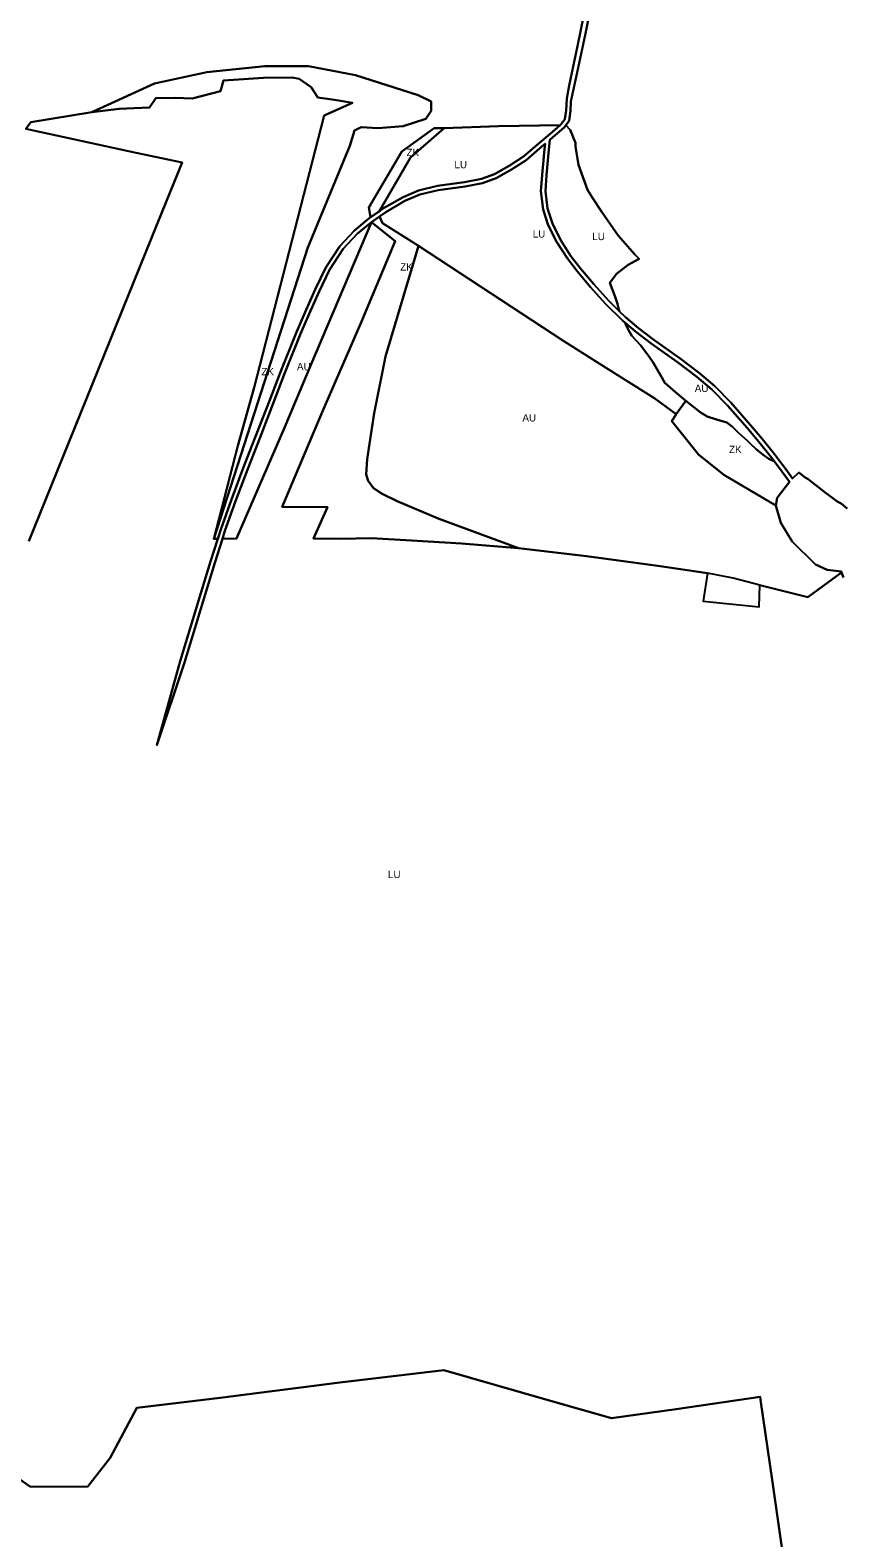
# Model space of a CAD drawing. Extents: x -532067 to -529270, y -1180561 to -1176456.
# Drawn here: x -530711 to -530157, y -1180006 to -1178979 of the extents above; entities that cross this region are included whole.
import ezdxf

# ---------------------------------------------------------------- set-up
doc = ezdxf.new("R2010")
doc.units = 0
for name, color, linetype in [('90630013', 7, 'Continuous'), ('90710013', 7, 'Continuous'), ('90750013', 7, 'Continuous'), ('90770013', 7, 'Continuous')]:
    doc.layers.add(name, color=color, linetype=linetype)

msp = doc.modelspace()

# ---------------------------------------------------------------- linework, layer by layer
at = {"layer": '90630013'}
for points in [[(-530156.3793, -1179351.78245), (-530157.6823, -1179348.30645), (-530157.8833, -1179347.77045), (-530167.3973, -1179346.65945), (-530175.3513, -1179342.90645), (-530191.2603, -1179327.14345), (-530199.0643, -1179314.53245), (-530202.3663, -1179302.67245), (-530201.4653, -1179297.56845), (-530193.1353, -1179286.54745), (-530198.0423, -1179279.73345), (-530203.3883, -1179272.71645), (-530205.7263, -1179269.64745), (-530214.0793, -1179259.22445), (-530221.9563, -1179249.81545), (-530235.4133, -1179234.46045), (-530245.9893, -1179223.61445), (-530256.2593, -1179214.87745), (-530269.4723, -1179204.98045), (-530287.4103, -1179192.17245), (-530298.0283, -1179184.12045), (-530305.4793, -1179177.85945), (-530306.9943, -1179176.58645), (-530318.5383, -1179165.17045), (-530328.8303, -1179153.81345), (-530337.9493, -1179143.05445), (-530344.5543, -1179134.39445), (-530351.8613, -1179123.13645), (-530357.5563, -1179111.59845), (-530361.0233, -1179100.80945), (-530362.5733, -1179088.50745), (-530361.8273, -1179077.33345), (-530360.0803, -1179059.81445), (-530359.7163, -1179056.17045), (-530361.6403, -1179057.82245), (-530372.6973, -1179067.31245), (-530382.6153, -1179073.61245), (-530393.0673, -1179079.63545), (-530402.3983, -1179082.92445), (-530414.2783, -1179085.26545), (-530432.6523, -1179087.80845), (-530445.1503, -1179090.72345), (-530455.2663, -1179095.12045), (-530468.2793, -1179102.64945), (-530472.5783, -1179105.64845), (-530478.1133, -1179109.50945), (-530479.3253, -1179110.35545), (-530487.8303, -1179117.53845), (-530497.4083, -1179127.77145), (-530506.6493, -1179141.98545), (-530513.7343, -1179156.76845), (-530520.6283, -1179172.07145), (-530526.4113, -1179185.60445), (-530537.5443, -1179213.39145), (-530544.8173, -1179232.46145), (-530554.3253, -1179256.83045), (-530562.4973, -1179277.70845), (-530570.8283, -1179299.72045), (-530578.0133, -1179320.06145), (-530579.6963, -1179325.36045), (-530584.9193, -1179341.80645), (-530593.0713, -1179368.59045), (-530605.5913, -1179409.72645), (-530624.4063, -1179466.13845), (-530608.4613, -1179408.85245), (-530595.9413, -1179367.71645), (-530587.7833, -1179340.91645), (-530582.8543, -1179325.39445), (-530580.8573, -1179319.10745), (-530573.6463, -1179298.69045), (-530565.2973, -1179276.63045), (-530557.1193, -1179255.73845), (-530547.6153, -1179231.38145), (-530540.3383, -1179212.29945), (-530529.1833, -1179184.45645), (-530523.3763, -1179170.86545), (-530516.4543, -1179155.50445), (-530509.2713, -1179140.51345), (-530499.7783, -1179125.91545), (-530489.9003, -1179115.36045), (-530481.1553, -1179107.97345), (-530478.6963, -1179106.25745), (-530472.8493, -1179102.17845), (-530469.8913, -1179100.11545), (-530456.6203, -1179092.43845), (-530446.0963, -1179087.86345), (-530433.2003, -1179084.85645), (-530414.7743, -1179082.30545), (-530403.1903, -1179080.02245), (-530394.3253, -1179076.89745), (-530384.1693, -1179071.04445), (-530374.4873, -1179064.89645), (-530363.5943, -1179055.54645), (-530356.6093, -1179049.55045), (-530349.5233, -1179043.46745), (-530348.7823, -1179042.83145), (-530346.1903, -1179039.23445), (-530345.3193, -1179033.50145), (-530345.0483, -1179025.15345), (-530343.2833, -1179016.29745), (-530337.4573, -1178988.49945), (-530327.5643, -1178940.45745)], [(-530326.8543, -1178953.76245), (-530332.4003, -1178981.99545), (-530338.9743, -1179012.70045), (-530342.1203, -1179027.39345), (-530342.3273, -1179033.77545), (-530343.3323, -1179040.40045), (-530345.5203, -1179043.43745), (-530346.5563, -1179044.87545), (-530354.6553, -1179051.82645), (-530356.4183, -1179053.34045), (-530357.0943, -1179060.11245), (-530358.8373, -1179077.58145), (-530359.5613, -1179088.41945), (-530358.0813, -1179100.15745), (-530354.7683, -1179110.47045), (-530349.2493, -1179121.65045), (-530342.1003, -1179132.66645), (-530335.6113, -1179141.17445), (-530326.5743, -1179151.83545), (-530316.3703, -1179163.09445), (-530308.9903, -1179170.39245), (-530304.9703, -1179174.36845), (-530296.1563, -1179181.77445), (-530285.6323, -1179189.75645), (-530267.7003, -1179202.55845), (-530254.3853, -1179212.53145), (-530243.9393, -1179221.42045), (-530233.2093, -1179232.42245), (-530219.6783, -1179247.86345), (-530211.7593, -1179257.32245), (-530203.3623, -1179267.79945), (-530197.8743, -1179275.00445), (-530195.6323, -1179277.94745), (-530191.1033, -1179284.23645), (-530186.8593, -1179280.13745), (-530182.5293, -1179283.55045), (-530180.5183, -1179284.79145), (-530178.1983, -1179286.65345), (-530175.2603, -1179288.82545), (-530173.0953, -1179290.53145), (-530168.7653, -1179293.78945), (-530164.5893, -1179297.04745), (-530161.6513, -1179299.21945), (-530159.6413, -1179300.46045), (-530157.9403, -1179301.39145), (-530153.9193, -1179304.64945)]]:
    msp.add_lwpolyline(points, dxfattribs=at)
at = {"layer": '90710013'}
for points in [[(-530489.0883, -1179009.38045), (-530446.2343, -1179022.97245), (-530437.5243, -1179027.32045), (-530437.5243, -1179033.65945), (-530441.0093, -1179039.04745), (-530449.4023, -1179041.78845), (-530456.5343, -1179044.11745), (-530473.6433, -1179045.38545), (-530485.0493, -1179044.75145), (-530489.8013, -1179046.97045), (-530492.9703, -1179057.42845), (-530521.4843, -1179126.83545), (-530585.6813, -1179325.42545), (-530569.3263, -1179262.08445), (-530558.1493, -1179222.29945), (-530520.3563, -1179075.69445), (-530510.4263, -1179036.80445), (-530491.0873, -1179028.23845), (-530503.3233, -1179026.20245), (-530514.7293, -1179024.56745), (-530519.2893, -1179017.55745), (-530527.3723, -1179011.89745), (-530532.2523, -1179010.97945), (-530551.6213, -1179011.13245), (-530578.9203, -1179012.96845), (-530581.0553, -1179020.31145), (-530600.2723, -1179025.36045), (-530611.8623, -1179024.74845), (-530625.1313, -1179025.05445), (-530629.4813, -1179031.33945), (-530650.1973, -1179032.27345), (-530668.8183, -1179034.60845), (-530626.0133, -1179015.13045), (-530590.4763, -1179007.28945), (-530550.7573, -1179003.10645), (-530520.9683, -1179003.10645)], [(-530472.8493, -1179102.17845), (-530478.6963, -1179106.25745), (-530479.8873, -1179099.61445), (-530457.3843, -1179061.31545), (-530435.3293, -1179045.37145), (-530428.5473, -1179045.37145), (-530451.5693, -1179065.37345)], [(-530432.7003, -1179311.59845), (-530377.9583, -1179331.84545), (-530416.6893, -1179328.60745), (-530450.7263, -1179326.54745), (-530478.0133, -1179325.07545), (-530499.7263, -1179325.37045), (-530517.5983, -1179325.25645), (-530508.0163, -1179303.83945), (-530539.1163, -1179303.50245), (-530511.7153, -1179239.08245), (-530485.3013, -1179178.41445), (-530461.9923, -1179122.46445), (-530478.0863, -1179109.65945), (-530478.1133, -1179109.50945), (-530472.5783, -1179105.64845), (-530470.5323, -1179110.26745), (-530454.6033, -1179120.15945), (-530446.0883, -1179125.73245), (-530447.9173, -1179131.84645), (-530468.6513, -1179201.15145), (-530476.2613, -1179239.73845), (-530480.9853, -1179271.17345), (-530481.7723, -1179281.67345), (-530480.4603, -1179285.87345), (-530476.7863, -1179290.86145), (-530470.7503, -1179294.79845), (-530460.5163, -1179299.78545)], [(-530201.4653, -1179297.56845), (-530202.3663, -1179302.67245), (-530237.8683, -1179281.80345), (-530255.2043, -1179267.98945), (-530273.4423, -1179245.27145), (-530270.3163, -1179240.44645), (-530263.8223, -1179231.27845), (-530253.9763, -1179239.02645), (-530249.3363, -1179241.97445), (-530242.8413, -1179244.14645), (-530235.8823, -1179246.16245), (-530232.0163, -1179249.11045), (-530227.8403, -1179253.14345), (-530221.8093, -1179258.72845), (-530219.6443, -1179260.74545), (-530215.9323, -1179264.31345), (-530211.1383, -1179268.19245), (-530207.2723, -1179270.98445), (-530203.3883, -1179272.71645), (-530198.0423, -1179279.73345), (-530193.1353, -1179286.54745)]]:
    msp.add_lwpolyline(points, close=True, dxfattribs=at)
at = {"layer": '90750013'}
for points in [[(-530327.5643, -1178940.45745), (-530337.4573, -1178988.49945), (-530343.2833, -1179016.29745), (-530345.0483, -1179025.15345), (-530345.3193, -1179033.50145), (-530346.1903, -1179039.23445), (-530348.7823, -1179042.83145), (-530349.5233, -1179043.46745), (-530391.6263, -1179044.11145), (-530428.5473, -1179045.37145), (-530435.3293, -1179045.37145), (-530457.3843, -1179061.31545), (-530479.8873, -1179099.61445), (-530478.6963, -1179106.25745), (-530481.1553, -1179107.97345), (-530489.9003, -1179115.36045), (-530499.7783, -1179125.91545), (-530509.2713, -1179140.51345), (-530516.4543, -1179155.50445), (-530523.3763, -1179170.86545), (-530529.1833, -1179184.45645), (-530540.3383, -1179212.29945), (-530547.6153, -1179231.38145), (-530557.1193, -1179255.73845), (-530565.2973, -1179276.63045), (-530573.6463, -1179298.69045), (-530580.8573, -1179319.10745), (-530582.8543, -1179325.39445), (-530585.6813, -1179325.42545), (-530521.4843, -1179126.83545), (-530492.9703, -1179057.42845), (-530489.8013, -1179046.97045), (-530485.0493, -1179044.75145), (-530473.6433, -1179045.38545), (-530456.5343, -1179044.11745), (-530449.4023, -1179041.78845), (-530441.0093, -1179039.04745), (-530437.5243, -1179033.65945), (-530437.5243, -1179027.32045), (-530446.2343, -1179022.97245), (-530489.0883, -1179009.38045), (-530520.9683, -1179003.10645), (-530550.7573, -1179003.10645), (-530590.4763, -1179007.28945), (-530626.0133, -1179015.13045), (-530668.8183, -1179034.60845), (-530710.4553, -1179041.28045), (-530713.8673, -1179045.84445), (-530638.6183, -1179062.40745), (-530607.2773, -1179068.78745), (-530624.0833, -1179110.25145), (-530692.4043, -1179279.29745), (-530711.6183, -1179327.08245)], [(-530153.9193, -1179304.64945), (-530157.9403, -1179301.39145), (-530159.6413, -1179300.46045), (-530161.6513, -1179299.21945), (-530164.5893, -1179297.04745), (-530168.7653, -1179293.78945), (-530173.0953, -1179290.53145), (-530175.2603, -1179288.82545), (-530178.1983, -1179286.65345), (-530180.5183, -1179284.79145), (-530182.5293, -1179283.55045), (-530186.8593, -1179280.13745), (-530191.1033, -1179284.23645), (-530195.6323, -1179277.94745), (-530197.8743, -1179275.00445), (-530203.3623, -1179267.79945), (-530211.7593, -1179257.32245), (-530219.6783, -1179247.86345), (-530233.2093, -1179232.42245), (-530243.9393, -1179221.42045), (-530254.3853, -1179212.53145), (-530267.7003, -1179202.55845), (-530285.6323, -1179189.75645), (-530296.1563, -1179181.77445), (-530304.9703, -1179174.36845), (-530308.9903, -1179170.39245), (-530309.5303, -1179169.18845), (-530310.4393, -1179165.17445), (-530311.8943, -1179160.43045), (-530315.7133, -1179150.94345), (-530310.9853, -1179144.74045), (-530303.1643, -1179138.72045), (-530295.5263, -1179134.52345), (-530298.5173, -1179131.66645), (-530309.8693, -1179118.71545), (-530320.7763, -1179102.86145), (-530327.8993, -1179092.36745), (-530330.7923, -1179087.45445), (-530337.0253, -1179070.48445), (-530339.0283, -1179057.97945), (-530339.0283, -1179055.52345), (-530342.5903, -1179046.59145), (-530345.5203, -1179043.43745), (-530343.3323, -1179040.40045), (-530342.3273, -1179033.77545), (-530342.1203, -1179027.39345), (-530338.9743, -1179012.70045), (-530332.4003, -1178981.99545), (-530326.8543, -1178953.76245)], [(-530738.3333, -1179952.54645), (-530710.5303, -1179971.53645), (-530671.4873, -1179971.33845), (-530656.2083, -1179951.88945), (-530638.1853, -1179917.86845), (-530581.2093, -1179911.06445), (-530499.6223, -1179900.56645), (-530428.7603, -1179892.11645), (-530357.5583, -1179912.56445), (-530314.3973, -1179924.94345), (-530270.4793, -1179918.60045), (-530213.0623, -1179910.37245), (-530212.6033, -1179914.01045), (-530205.0143, -1179966.75845), (-530192.0373, -1180057.25345)]]:
    msp.add_lwpolyline(points, dxfattribs=at)
for points in [[(-530570.0483, -1179325.25645), (-530579.6963, -1179325.36045), (-530578.0133, -1179320.06145), (-530570.8283, -1179299.72045), (-530562.4973, -1179277.70845), (-530554.3253, -1179256.83045), (-530544.8173, -1179232.46145), (-530537.5443, -1179213.39145), (-530526.4113, -1179185.60445), (-530520.6283, -1179172.07145), (-530513.7343, -1179156.76845), (-530506.6493, -1179141.98545), (-530497.4083, -1179127.77145), (-530487.8303, -1179117.53845), (-530479.3253, -1179110.35545), (-530478.1133, -1179109.50945), (-530478.0863, -1179109.65945), (-530519.1543, -1179206.25045), (-530537.7453, -1179250.23245), (-530560.6433, -1179303.16745)], [(-530157.6823, -1179348.30645), (-530180.6043, -1179365.16645), (-530213.2693, -1179356.91845), (-530231.5543, -1179352.19945), (-530248.9843, -1179348.76645), (-530282.9893, -1179343.83245), (-530331.5983, -1179337.14345), (-530377.9583, -1179331.84545), (-530432.7003, -1179311.59845), (-530460.5163, -1179299.78545), (-530470.7503, -1179294.79845), (-530476.7863, -1179290.86145), (-530480.4603, -1179285.87345), (-530481.7723, -1179281.67345), (-530480.9853, -1179271.17345), (-530476.2613, -1179239.73845), (-530468.6513, -1179201.15145), (-530447.9173, -1179131.84645), (-530446.0883, -1179125.73245), (-530347.6493, -1179190.15545), (-530322.8373, -1179205.97545), (-530284.9993, -1179229.75745), (-530270.3163, -1179240.44645), (-530273.4423, -1179245.27145), (-530255.2043, -1179267.98945), (-530237.8683, -1179281.80345), (-530202.3663, -1179302.67245), (-530199.0643, -1179314.53245), (-530191.2603, -1179327.14345), (-530175.3513, -1179342.90645), (-530167.3973, -1179346.65945), (-530157.8833, -1179347.77045)], [(-530205.7263, -1179269.64745), (-530203.3883, -1179272.71645), (-530207.2723, -1179270.98445), (-530211.1383, -1179268.19245), (-530215.9323, -1179264.31345), (-530219.6443, -1179260.74545), (-530221.8093, -1179258.72845), (-530227.8403, -1179253.14345), (-530232.0163, -1179249.11045), (-530235.8823, -1179246.16245), (-530242.8413, -1179244.14645), (-530249.3363, -1179241.97445), (-530253.9763, -1179239.02645), (-530263.8223, -1179231.27845), (-530270.7973, -1179225.48845), (-530278.0123, -1179218.97445), (-530281.1383, -1179213.90745), (-530283.5433, -1179209.56445), (-530286.1893, -1179205.22245), (-530289.0753, -1179200.87945), (-530294.6073, -1179193.40045), (-530297.4933, -1179190.50445), (-530300.6193, -1179187.12745), (-530303.0243, -1179182.78445), (-530304.7083, -1179179.40645), (-530305.4793, -1179177.85945), (-530298.0283, -1179184.12045), (-530287.4103, -1179192.17245), (-530269.4723, -1179204.98045), (-530256.2593, -1179214.87745), (-530245.9893, -1179223.61445), (-530235.4133, -1179234.46045), (-530221.9563, -1179249.81545), (-530214.0793, -1179259.22445)]]:
    msp.add_lwpolyline(points, close=True, dxfattribs=at)
at = {"layer": '90770013'}
for points in [[(-530711.6183, -1179327.08245), (-530692.4043, -1179279.29745), (-530624.0833, -1179110.25145), (-530607.2773, -1179068.78745), (-530638.6183, -1179062.40745), (-530713.8673, -1179045.84445), (-530710.4553, -1179041.28045), (-530668.8183, -1179034.60845), (-530650.1973, -1179032.27345), (-530629.4813, -1179031.33945), (-530625.1313, -1179025.05445), (-530611.8623, -1179024.74845), (-530600.2723, -1179025.36045), (-530581.0553, -1179020.31145), (-530578.9203, -1179012.96845), (-530551.6213, -1179011.13245), (-530532.2523, -1179010.97945), (-530527.3723, -1179011.89745), (-530519.2893, -1179017.55745), (-530514.7293, -1179024.56745), (-530503.3233, -1179026.20245), (-530491.0873, -1179028.23845), (-530510.4263, -1179036.80445), (-530520.3563, -1179075.69445), (-530558.1493, -1179222.29945), (-530569.3263, -1179262.08445), (-530585.6813, -1179325.42545), (-530582.8543, -1179325.39445), (-530587.7833, -1179340.91645), (-530595.9413, -1179367.71645), (-530608.4613, -1179408.85245), (-530624.4063, -1179466.13845), (-530605.5913, -1179409.72645), (-530593.0713, -1179368.59045), (-530584.9193, -1179341.80645), (-530579.6963, -1179325.36045), (-530570.0483, -1179325.25645), (-530560.6433, -1179303.16745), (-530537.7453, -1179250.23245), (-530519.1543, -1179206.25045), (-530478.0863, -1179109.65945), (-530461.9923, -1179122.46445), (-530485.3013, -1179178.41445), (-530511.7153, -1179239.08245), (-530539.1163, -1179303.50245), (-530508.0163, -1179303.83945), (-530517.5983, -1179325.25645), (-530499.7263, -1179325.37045), (-530478.0133, -1179325.07545), (-530450.7263, -1179326.54745), (-530416.6893, -1179328.60745), (-530377.9583, -1179331.84545), (-530331.5983, -1179337.14345), (-530282.9893, -1179343.83245), (-530248.9843, -1179348.76645), (-530252.0853, -1179367.86045), (-530213.8043, -1179371.82945), (-530213.2693, -1179356.91845), (-530180.6043, -1179365.16645), (-530157.6823, -1179348.30645), (-530156.3793, -1179351.78245)], [(-530192.0373, -1180057.25345), (-530205.0143, -1179966.75845), (-530212.6033, -1179914.01045), (-530213.0623, -1179910.37245), (-530270.4793, -1179918.60045), (-530314.3973, -1179924.94345), (-530357.5583, -1179912.56445), (-530428.7603, -1179892.11645), (-530499.6223, -1179900.56645), (-530581.2093, -1179911.06445), (-530638.1853, -1179917.86845), (-530656.2083, -1179951.88945), (-530671.4873, -1179971.33845), (-530710.5303, -1179971.53645), (-530738.3333, -1179952.54645)]]:
    msp.add_lwpolyline(points, dxfattribs=at)
for points in [[(-530469.8913, -1179100.11545), (-530472.8493, -1179102.17845), (-530451.5693, -1179065.37345), (-530428.5473, -1179045.37145), (-530391.6263, -1179044.11145), (-530349.5233, -1179043.46745), (-530356.6093, -1179049.55045), (-530363.5943, -1179055.54645), (-530374.4873, -1179064.89645), (-530384.1693, -1179071.04445), (-530394.3253, -1179076.89745), (-530403.1903, -1179080.02245), (-530414.7743, -1179082.30545), (-530433.2003, -1179084.85645), (-530446.0963, -1179087.86345), (-530456.6203, -1179092.43845)], [(-530309.5303, -1179169.18845), (-530308.9903, -1179170.39245), (-530316.3703, -1179163.09445), (-530326.5743, -1179151.83545), (-530335.6113, -1179141.17445), (-530342.1003, -1179132.66645), (-530349.2493, -1179121.65045), (-530354.7683, -1179110.47045), (-530358.0813, -1179100.15745), (-530359.5613, -1179088.41945), (-530358.8373, -1179077.58145), (-530357.0943, -1179060.11245), (-530356.4183, -1179053.34045), (-530354.6553, -1179051.82645), (-530346.5563, -1179044.87545), (-530345.5203, -1179043.43745), (-530342.5903, -1179046.59145), (-530339.0283, -1179055.52345), (-530339.0283, -1179057.97945), (-530337.0253, -1179070.48445), (-530330.7923, -1179087.45445), (-530327.8993, -1179092.36745), (-530320.7763, -1179102.86145), (-530309.8693, -1179118.71545), (-530298.5173, -1179131.66645), (-530295.5263, -1179134.52345), (-530303.1643, -1179138.72045), (-530310.9853, -1179144.74045), (-530315.7133, -1179150.94345), (-530311.8943, -1179160.43045), (-530310.4393, -1179165.17445)], [(-530263.8223, -1179231.27845), (-530270.3163, -1179240.44645), (-530284.9993, -1179229.75745), (-530322.8373, -1179205.97545), (-530347.6493, -1179190.15545), (-530446.0883, -1179125.73245), (-530454.6033, -1179120.15945), (-530470.5323, -1179110.26745), (-530472.5783, -1179105.64845), (-530468.2793, -1179102.64945), (-530455.2663, -1179095.12045), (-530445.1503, -1179090.72345), (-530432.6523, -1179087.80845), (-530414.2783, -1179085.26545), (-530402.3983, -1179082.92445), (-530393.0673, -1179079.63545), (-530382.6153, -1179073.61245), (-530372.6973, -1179067.31245), (-530361.6403, -1179057.82245), (-530359.7163, -1179056.17045), (-530360.0803, -1179059.81445), (-530361.8273, -1179077.33345), (-530362.5733, -1179088.50745), (-530361.0233, -1179100.80945), (-530357.5563, -1179111.59845), (-530351.8613, -1179123.13645), (-530344.5543, -1179134.39445), (-530337.9493, -1179143.05445), (-530328.8303, -1179153.81345), (-530318.5383, -1179165.17045), (-530306.9943, -1179176.58645), (-530305.4793, -1179177.85945), (-530304.7083, -1179179.40645), (-530303.0243, -1179182.78445), (-530300.6193, -1179187.12745), (-530297.4933, -1179190.50445), (-530294.6073, -1179193.40045), (-530289.0753, -1179200.87945), (-530286.1893, -1179205.22245), (-530283.5433, -1179209.56445), (-530281.1383, -1179213.90745), (-530278.0123, -1179218.97445), (-530270.7973, -1179225.48845)]]:
    msp.add_lwpolyline(points, close=True, dxfattribs=at)

# ---------------------------------------------------------------- texts
at = {"layer": '90710013'}
for rotation, p in [(359.99999999, (-530454.2173, -1179064.48964)), (359.99999997, (-530458.5373, -1179142.53052)), (359.99999998, (-530553.1713, -1179213.92325)), (0.00000003, (-530234.33036, -1179266.97545))]:
    msp.add_text('ZK', height=5, rotation=rotation, dxfattribs=at).set_placement(p)
at = {"layer": '90750013'}
for rotation, p in [(0.00000002, (-530528.8913, -1179210.54013)), (0.00000001, (-530257.68842, -1179225.28795)), (359.99999997, (-530375.20947, -1179245.44945))]:
    msp.add_text('AU', height=5, rotation=rotation, dxfattribs=at).set_placement(p)
at = {"layer": '90770013'}
for rotation, p in [(360, (-530421.56589, -1179072.82295)), (359.99999998, (-530368.2003, -1179120.07935)), (0.00000003, (-530327.5438, -1179121.79146)), (0.00000006, (-530466.83852, -1179556.64145))]:
    msp.add_text('LU', height=5, rotation=rotation, dxfattribs=at).set_placement(p)

doc.saveas('drawing.dxf')
